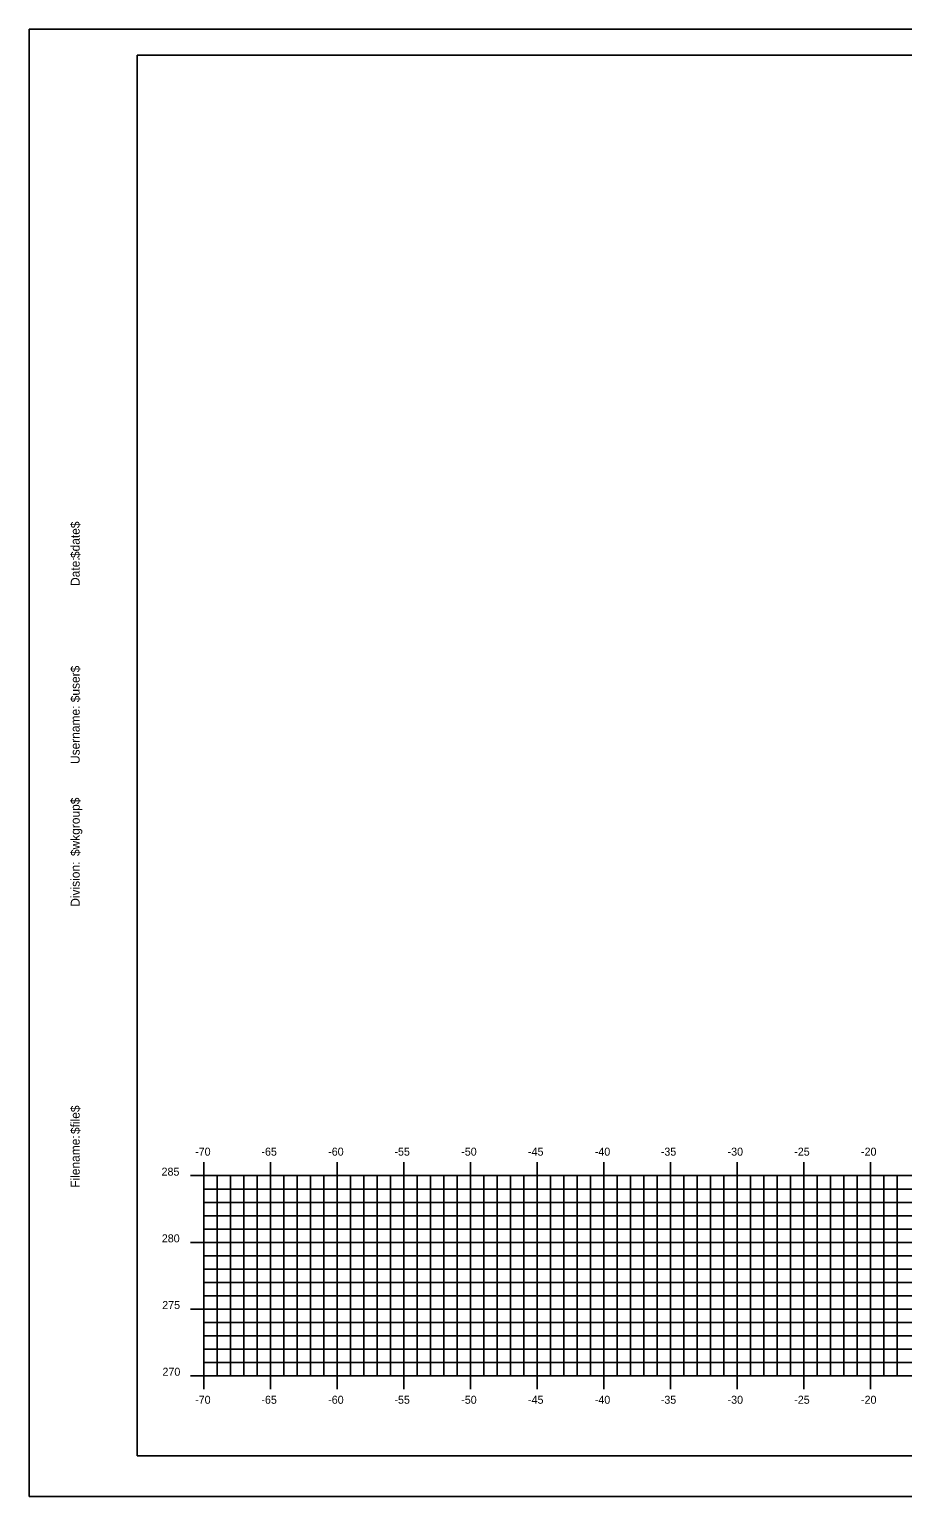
# Model space of a CAD drawing. Extents: x 850898 to 851068, y 366543 to 366653.
# Drawn here: x 850898.4 to 850963.9, y 366542.9 to 366652.9 of the extents above; entities that cross this region are included whole.
import ezdxf

# ---------------------------------------------------------------- set-up
doc = ezdxf.new("R2010")
doc.units = 0
for name, color, linetype in [('BORDER', 7, 'Continuous'), ('H_V ANNOTATION', 7, 'Continuous'), ('MAJOR', 7, 'Continuous'), ('MINOR', 7, 'Continuous'), ('PLOT BOUNDARY', 7, 'Continuous')]:
    doc.layers.add(name, color=color, linetype=linetype)

msp = doc.modelspace()

# ---------------------------------------------------------------- linework, layer by layer
at = {"layer": 'BORDER'}
for p, q in [((851066.48, 366650.99), (850906.48, 366650.99)), ((850906.48, 366650.99), (850906.48, 366545.99)), ((850906.48, 366545.99), (851066.48, 366545.99))]:
    msp.add_line(p, q, dxfattribs=at)
at = {"layer": 'MAJOR'}
for p, q in [((850911.47, 366567.99), (850911.47, 366566.99)), ((850916.47, 366567.99), (850916.47, 366566.99)), ((850921.47, 366567.99), (850921.47, 366566.99)), ((850926.47, 366567.99), (850926.47, 366566.99)), ((850931.47, 366567.99), (850931.47, 366566.99)), ((850936.47, 366567.99), (850936.47, 366566.99)), ((850941.47, 366567.99), (850941.47, 366566.99)), ((850946.47, 366567.99), (850946.47, 366566.99)), ((850951.47, 366567.99), (850951.47, 366566.99)), ((850956.47, 366567.99), (850956.47, 366566.99)), ((850961.47, 366567.99), (850961.47, 366566.99)), ((850910.47, 366566.99), (850911.47, 366566.99)), ((850911.47, 366566.99), (851051.47, 366566.99)), ((850911.47, 366551.99), (850911.47, 366566.99)), ((850911.47, 366551.99), (850911.47, 366566.99)), ((850911.47, 366566.99), (851051.47, 366566.99)), ((850916.47, 366551.99), (850916.47, 366566.99)), ((850921.47, 366551.99), (850921.47, 366566.99)), ((850926.47, 366551.99), (850926.47, 366566.99)), ((850931.47, 366551.99), (850931.47, 366566.99)), ((850936.47, 366551.99), (850936.47, 366566.99)), ((850941.47, 366551.99), (850941.47, 366566.99)), ((850946.47, 366551.99), (850946.47, 366566.99)), ((850951.47, 366551.99), (850951.47, 366566.99)), ((850956.47, 366551.99), (850956.47, 366566.99)), ((850961.47, 366551.99), (850961.47, 366566.99)), ((850910.47, 366561.99), (850911.47, 366561.99)), ((850911.47, 366561.99), (851051.47, 366561.99)), ((850910.47, 366556.99), (850911.47, 366556.99)), ((850911.47, 366556.99), (851051.47, 366556.99)), ((850910.47, 366551.99), (850911.47, 366551.99)), ((850911.47, 366551.99), (851051.47, 366551.99)), ((850911.47, 366551.99), (851051.47, 366551.99)), ((850911.47, 366550.98), (850911.47, 366551.99)), ((850916.47, 366550.98), (850916.47, 366551.99)), ((850921.47, 366550.98), (850921.47, 366551.99)), ((850926.47, 366550.98), (850926.47, 366551.99)), ((850931.47, 366550.98), (850931.47, 366551.99)), ((850936.47, 366550.98), (850936.47, 366551.99)), ((850941.47, 366550.98), (850941.47, 366551.99)), ((850946.47, 366550.98), (850946.47, 366551.99)), ((850951.47, 366550.98), (850951.47, 366551.99)), ((850956.47, 366550.98), (850956.47, 366551.99)), ((850961.47, 366550.98), (850961.47, 366551.99))]:
    msp.add_line(p, q, dxfattribs=at)
at = {"layer": 'MINOR'}
for p, q in [((850912.47, 366551.99), (850912.47, 366566.99)), ((850913.47, 366551.99), (850913.47, 366566.99)), ((850914.47, 366551.99), (850914.47, 366566.99)), ((850915.47, 366551.99), (850915.47, 366566.99)), ((850917.47, 366551.99), (850917.47, 366566.99)), ((850918.47, 366551.99), (850918.47, 366566.99)), ((850919.47, 366551.99), (850919.47, 366566.99)), ((850920.47, 366551.99), (850920.47, 366566.99)), ((850922.47, 366551.99), (850922.47, 366566.99)), ((850923.47, 366551.99), (850923.47, 366566.99)), ((850924.47, 366551.99), (850924.47, 366566.99)), ((850925.47, 366551.99), (850925.47, 366566.99)), ((850927.47, 366551.99), (850927.47, 366566.99)), ((850928.47, 366551.99), (850928.47, 366566.99)), ((850929.47, 366551.99), (850929.47, 366566.99)), ((850930.47, 366551.99), (850930.47, 366566.99)), ((850932.47, 366551.99), (850932.47, 366566.99)), ((850933.47, 366551.99), (850933.47, 366566.99)), ((850934.47, 366551.99), (850934.47, 366566.99)), ((850935.47, 366551.99), (850935.47, 366566.99)), ((850937.47, 366551.99), (850937.47, 366566.99)), ((850938.47, 366551.99), (850938.47, 366566.99)), ((850939.47, 366551.99), (850939.47, 366566.99)), ((850940.47, 366551.99), (850940.47, 366566.99)), ((850942.47, 366551.99), (850942.47, 366566.99)), ((850943.47, 366551.99), (850943.47, 366566.99)), ((850944.47, 366551.99), (850944.47, 366566.99)), ((850945.47, 366551.99), (850945.47, 366566.99)), ((850947.47, 366551.99), (850947.47, 366566.99)), ((850948.47, 366551.99), (850948.47, 366566.99)), ((850949.47, 366551.99), (850949.47, 366566.99)), ((850950.47, 366551.99), (850950.47, 366566.99)), ((850952.47, 366551.99), (850952.47, 366566.99)), ((850953.47, 366551.99), (850953.47, 366566.99)), ((850954.47, 366551.99), (850954.47, 366566.99)), ((850955.47, 366551.99), (850955.47, 366566.99)), ((850957.47, 366551.99), (850957.47, 366566.99)), ((850958.47, 366551.99), (850958.47, 366566.99)), ((850959.47, 366551.99), (850959.47, 366566.99)), ((850960.47, 366551.99), (850960.47, 366566.99)), ((850962.47, 366551.99), (850962.47, 366566.99)), ((850963.47, 366551.99), (850963.47, 366566.99)), ((850911.47, 366565.99), (851051.47, 366565.99)), ((850911.47, 366565.99), (850912.48, 366565.99)), ((850911.47, 366564.99), (851051.47, 366564.99)), ((850911.47, 366564.99), (850912.48, 366564.99)), ((850911.47, 366563.99), (851051.47, 366563.99)), ((850911.47, 366563.99), (850912.48, 366563.99)), ((850911.47, 366562.99), (851051.47, 366562.99)), ((850911.47, 366562.99), (850912.48, 366562.99)), ((850911.47, 366560.99), (851051.47, 366560.99)), ((850911.47, 366560.99), (850912.48, 366560.99)), ((850911.47, 366559.99), (851051.47, 366559.99)), ((850911.47, 366559.99), (850912.48, 366559.99)), ((850911.47, 366558.99), (851051.47, 366558.99)), ((850911.47, 366558.99), (850912.48, 366558.99)), ((850911.47, 366557.99), (851051.47, 366557.99)), ((850911.47, 366557.99), (850912.48, 366557.99)), ((850911.47, 366555.99), (851051.47, 366555.99)), ((850911.47, 366555.99), (850912.48, 366555.99)), ((850911.47, 366554.99), (851051.47, 366554.99)), ((850911.47, 366554.99), (850912.48, 366554.99)), ((850911.47, 366553.99), (851051.47, 366553.99)), ((850911.47, 366553.99), (850912.48, 366553.99)), ((850911.47, 366552.99), (851051.47, 366552.99)), ((850911.47, 366552.99), (850912.48, 366552.99))]:
    msp.add_line(p, q, dxfattribs=at)
at = {"layer": 'PLOT BOUNDARY'}
msp.add_lwpolyline([(850898.38, 366542.93), (851068.38, 366542.93), (851068.38, 366652.93), (850898.38, 366652.93)], close=True, dxfattribs=at)

# ---------------------------------------------------------------- texts
at = {"layer": 'BORDER'}
for s, p in [('$date$', (850902.16, 366613.29)), ('Date:', (850902.16, 366611.2)), ('$user$', (850902.16, 366602.48)), ('Username:', (850902.16, 366597.85)), ('$wkgroup$', (850902.16, 366590.95)), ('Division:', (850902.16, 366587.15)), ('$file$', (850902.16, 366570.11)), ('Filename:', (850902.16, 366566.08))]:
    msp.add_text(s, height=0.67, rotation=90, dxfattribs=at).set_placement(p)
at = {"layer": 'H_V ANNOTATION'}
for s, p in [('-70', (850910.82, 366568.49)), ('-65', (850915.79, 366568.49)), ('-60', (850920.8, 366568.49)), ('-55', (850925.77, 366568.49)), ('-50', (850930.78, 366568.49)), ('-45', (850935.79, 366568.49)), ('-40', (850940.8, 366568.49)), ('-35', (850945.75, 366568.49)), ('-30', (850950.76, 366568.49)), ('-25', (850955.76, 366568.49)), ('-20', (850960.77, 366568.49)), ('285', (850908.3, 366566.99)), ('280', (850908.32, 366561.99)), ('275', (850908.35, 366556.99)), ('270', (850908.37, 366551.99)), ('-70', (850910.82, 366549.89)), ('-65', (850915.79, 366549.89)), ('-60', (850920.8, 366549.89)), ('-55', (850925.77, 366549.89)), ('-50', (850930.78, 366549.89)), ('-45', (850935.79, 366549.89)), ('-40', (850940.8, 366549.89)), ('-35', (850945.75, 366549.89)), ('-30', (850950.76, 366549.89)), ('-25', (850955.76, 366549.89)), ('-20', (850960.77, 366549.89))]:
    msp.add_text(s, height=0.6, dxfattribs=at).set_placement(p)

doc.saveas('drawing.dxf')
